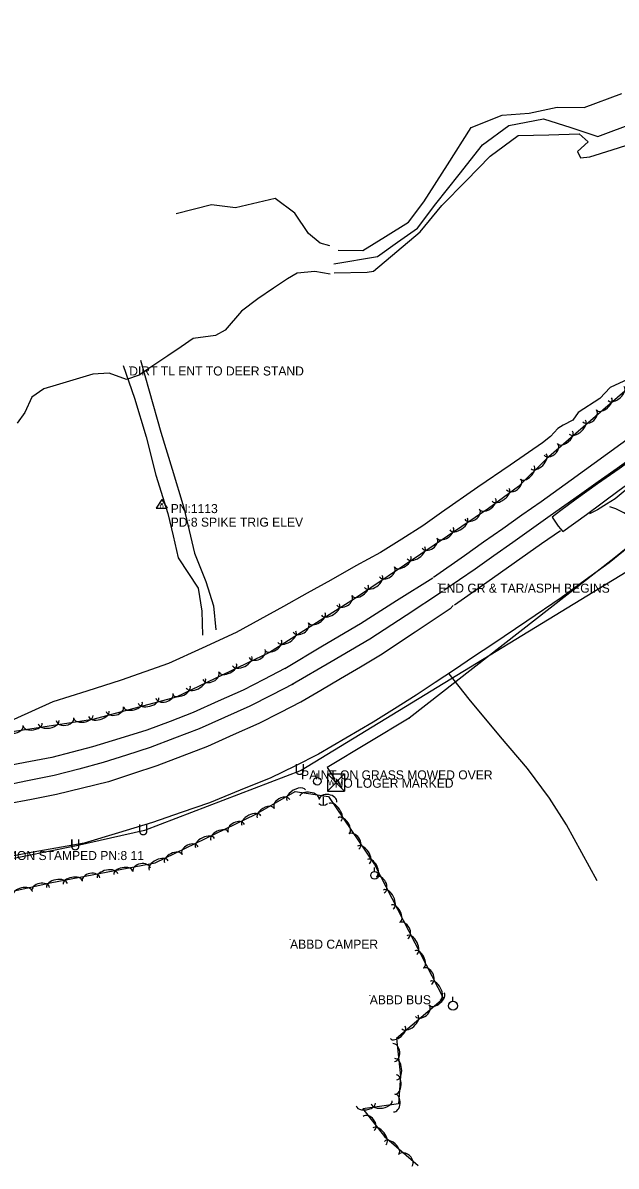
# Model space of a CAD drawing. Extents: x 1451369 to 1458940, y 1868647 to 1875095.
# Drawn here: x 1453703 to 1454031, y 1870905 to 1871537 of the extents above; entities that cross this region are included whole.
import ezdxf

# ---------------------------------------------------------------- set-up
doc = ezdxf.new("R2010")
doc.units = 0
for name, color, linetype in [('Default', 7, 'Continuous'), ('E_Const Align', 7, 'Continuous'), ('E_No Plot', 7, 'Continuous'), ('E_Proposed ROW and Easements', 7, 'Continuous'), ('E_Quarter Section Line', 7, 'Continuous'), ('E_ROW Point Number', 7, 'Continuous'), ('E_Station Offset', 7, 'Continuous'), ('E_Survey Point Number', 7, 'Continuous'), ('E_Tract Residual', 7, 'Continuous'), ('S_EDGE_PAVEMENT', 7, 'Continuous'), ('S_EXIST_ROW', 7, 'Continuous'), ('S_PARKING', 7, 'Continuous'), ('S_PAVEMENT_CROWN', 7, 'Continuous'), ('S_PRIMARY_CTL_ANNOT', 7, 'Continuous'), ('S_SECONDARY_CTL_ANNOT', 7, 'Continuous'), ('S_SURVEY_TEXT_ANNOT', 7, 'Continuous'), ('S_TRAILS', 7, 'Continuous'), ('S_UNDERGROUND_CABLE_ANNOT', 7, 'Continuous'), ('S_WATER_UTILITIES_ANNOT', 7, 'Continuous')]:
    doc.layers.add(name, color=color, linetype=linetype)

msp = doc.modelspace()

# ---------------------------------------------------------------- linework, layer by layer
at = {"layer": 'E_Const Align'}
for p, q in [((1453865.48, 1871119.86), (1453865.48, 1871121.97)), ((1453868.77, 1871109.2), (1453868.77, 1871104.47)), ((1453897.18, 1871067.82), (1453897.18, 1871069.93)), ((1453940.55, 1870996.01), (1453940.55, 1870998.49))]:
    msp.add_line(p, q, dxfattribs=at)
for centre, radius in [((1453865.6, 1871117.72), 2.13), ((1453897.31, 1871065.68), 2.13), ((1453940.7, 1870993.49), 2.5)]:
    msp.add_circle(centre, radius, dxfattribs=at)
msp.add_arc((1453868.83, 1871107.9), 3.41, 226.39718, 313.60282, dxfattribs=at)
at = {"layer": 'E_No Plot'}
for points in [[(1454029.66, 1871241.04), (1454029.66, 1871241.09), (1454029.66, 1871241.04), (1454029.61, 1871241.04), (1454029.66, 1871241.04), (1454029.66, 1871240.99), (1454029.66, 1871241.04), (1454029.71, 1871241.04)], [(1453916.5, 1871152.6), (1453916.5, 1871152.65), (1453916.5, 1871152.6), (1453916.45, 1871152.6), (1453916.5, 1871152.6), (1453916.5, 1871152.55), (1453916.5, 1871152.6), (1453916.55, 1871152.6)], [(1453871.11, 1871125.35), (1453871.11, 1871125.4), (1453871.11, 1871125.35), (1453871.06, 1871125.35), (1453871.11, 1871125.35), (1453871.11, 1871125.3), (1453871.11, 1871125.35), (1453871.16, 1871125.35)], [(1453875.2, 1871119.13), (1453875.2, 1871119.18), (1453875.2, 1871119.13), (1453875.15, 1871119.13), (1453875.2, 1871119.13), (1453875.2, 1871119.08), (1453875.2, 1871119.13), (1453875.25, 1871119.13)]]:
    msp.add_lwpolyline(points, dxfattribs=at)
at = {"layer": 'E_Proposed ROW and Easements'}
for points in [[(1453761.61, 1871347.23), (1453761.61, 1871347.28), (1453761.61, 1871347.23), (1453761.56, 1871347.23), (1453761.61, 1871347.23), (1453761.61, 1871347.18), (1453761.61, 1871347.23), (1453761.66, 1871347.23)], [(1453932.64, 1871227.05), (1453932.64, 1871227.1), (1453932.64, 1871227.05), (1453932.59, 1871227.05), (1453932.64, 1871227.05), (1453932.64, 1871227), (1453932.64, 1871227.05), (1453932.69, 1871227.05)], [(1453850.57, 1871030.07), (1453850.57, 1871030.12), (1453850.57, 1871030.07), (1453850.52, 1871030.07), (1453850.57, 1871030.07), (1453850.57, 1871030.02), (1453850.57, 1871030.07), (1453850.62, 1871030.07)], [(1453894.65, 1870999.32), (1453894.65, 1870999.37), (1453894.65, 1870999.32), (1453894.6, 1870999.32), (1453894.65, 1870999.32), (1453894.65, 1870999.27), (1453894.65, 1870999.32), (1453894.7, 1870999.32)]]:
    msp.add_lwpolyline(points, dxfattribs=at)
at = {"layer": 'E_Quarter Section Line'}
for p, q in [((1454074.79, 1871277.88), (1454029.66, 1871241.04)), ((1454029.66, 1871241.04), (1453916.5, 1871152.6)), ((1453916.5, 1871152.6), (1453871.11, 1871125.35)), ((1453871.11, 1871125.35), (1453875.2, 1871119.13)), ((1453871.33, 1871121.79), (1453880.67, 1871121.79)), ((1453871.33, 1871121.79), (1453871.33, 1871112.29)), ((1453871.33, 1871121.79), (1453880.67, 1871112.29)), ((1453880.67, 1871121.79), (1453871.33, 1871112.29)), ((1453880.67, 1871121.79), (1453880.67, 1871112.29)), ((1453871.33, 1871112.29), (1453880.67, 1871112.29))]:
    msp.add_line(p, q, dxfattribs=at)
at = {"layer": 'E_ROW Point Number'}
for points in [[(1454039.82, 1871337.12), (1453992.45, 1871296.2), (1453976.82, 1871280.78), (1453960.32, 1871268.68), (1453922.85, 1871243.35), (1453886.25, 1871218.61), (1453839.09, 1871189.03), (1453787.52, 1871164.25), (1453741.45, 1871151.98), (1453664.24, 1871140.16), (1453599.61, 1871130.45), (1453561.1, 1871125.93), (1453518.5, 1871126.32), (1453491.52, 1871121.48), (1453464.98, 1871114.18), (1453434.82, 1871115.78), (1453406.63, 1871118.92), (1453377.62, 1871115.67), (1453346.72, 1871118.15), (1453318.09, 1871119.73), (1453254.46, 1871123.88)], [(1453227.7, 1871010.68), (1453313.58, 1871012.86), (1453360.11, 1871017.03), (1453439.31, 1871020.86), (1453498.37, 1871025.17), (1453554.25, 1871028.97), (1453592.3, 1871033.98), (1453641.4, 1871044.5), (1453718.76, 1871061.66), (1453776, 1871072.6), (1453831.69, 1871099.59), (1453853.3, 1871112.04), (1453871.84, 1871109.31), (1453897.32, 1871071.61), (1453935.46, 1870997.61), (1453909.48, 1870975.45), (1453911.54, 1870954.62), (1453910.44, 1870939.28), (1453890.79, 1870936.46), (1453902.73, 1870921.25), (1453921.42, 1870905.04)]]:
    msp.add_lwpolyline(points, dxfattribs=at)
for centre, major_axis, ratio, start_param, end_param in [((1454030.95, 1871332.26), (4.44, 3.84), 0.550096, 3.141615, 6.283208), ((1454024.24, 1871326.46), (4.05, 3.49), 0.540715, 3.141614, 6.283207), ((1454016.27, 1871319.92), (3.75, 3.24), 0.685331, 3.141629, 6.283222), ((1454009.44, 1871313.67), (4.44, 3.84), 0.550096, 3.141615, 6.283208), ((1454002.73, 1871307.87), (4.05, 3.49), 0.540715, 3.141614, 6.283207), ((1453994.76, 1871301.34), (3.75, 3.24), 0.685331, 3.141629, 6.283222), ((1453988.01, 1871294.79), (4.18, 4.12), 0.550077, 3.141593, 6.283185), ((1453981.69, 1871288.57), (3.81, 3.75), 0.540697, 3.141593, 6.283185), ((1453974.31, 1871281.89), (3.99, 2.93), 0.686162, 3.141842, 6.283435), ((1453967.01, 1871276.22), (4.73, 3.47), 0.550763, 3.141745, 6.283338), ((1453951.27, 1871265.44), (4.11, 2.78), 0.685305, 3.141593, 6.283185), ((1453959.87, 1871270.98), (4.31, 3.16), 0.541371, 3.14174, 6.283333), ((1453943.75, 1871260.04), (4.86, 3.29), 0.550075, 3.141593, 6.283185), ((1453936.4, 1871255.07), (4.43, 2.99), 0.540695, 3.141593, 6.283185), ((1453927.72, 1871249.52), (4.11, 2.78), 0.685305, 3.141593, 6.283185), ((1453920.2, 1871244.12), (4.86, 3.29), 0.550075, 3.141593, 6.283185), ((1453904.17, 1871233.6), (4.11, 2.78), 0.685305, 3.141593, 6.283185), ((1453912.85, 1871239.15), (4.43, 2.99), 0.540695, 3.141593, 6.283185), ((1453896.65, 1871228.19), (4.86, 3.29), 0.550075, 3.141593, 6.283185), ((1453889.3, 1871223.23), (4.43, 2.99), 0.540695, 3.141593, 6.283185), ((1453880.59, 1871217.87), (4.2, 2.63), 0.685304, 3.141593, 6.283185), ((1453872.89, 1871212.73), (4.97, 3.12), 0.550075, 3.141593, 6.283185), ((1453856.51, 1871202.76), (4.2, 2.63), 0.685304, 3.141593, 6.283185), ((1453865.37, 1871208.02), (4.53, 2.84), 0.540694, 3.141593, 6.283185), ((1453848.8, 1871197.62), (4.97, 3.12), 0.550075, 3.141593, 6.283185), ((1453841.29, 1871192.91), (4.53, 2.84), 0.540694, 3.141593, 6.283185), ((1453824.08, 1871184.17), (5.29, 2.54), 0.550073, 3.141593, 6.283185), ((1453832.31, 1871188.41), (4.47, 2.15), 0.685302, 3.141593, 6.283185), ((1453816.09, 1871180.33), (4.82, 2.31), 0.540693, 3.141593, 6.283185), ((1453798.45, 1871171.86), (5.29, 2.54), 0.550073, 3.141593, 6.283185), ((1453806.69, 1871176.11), (4.47, 2.15), 0.685302, 3.141593, 6.283185), ((1453790.46, 1871168.02), (4.82, 2.31), 0.540693, 3.141593, 6.283185), ((1453763.64, 1871160.09), (5.17, 1.38), 0.54069, 3.141593, 6.283185), ((1453772.21, 1871162.37), (5.67, 1.51), 0.55007, 3.141593, 6.283185), ((1453781.09, 1871165.01), (4.79, 1.28), 0.685299, 3.141593, 6.283185), ((1453736.29, 1871153.33), (5.28, 0.81), 0.541194, 3.141797, 6.28339), ((1453744.74, 1871155.05), (5.67, 1.51), 0.55007, 3.141593, 6.283185), ((1453753.62, 1871157.69), (4.79, 1.28), 0.685299, 3.141593, 6.283185), ((1453698, 1871147.74), (4.89, 0.75), 0.685937, 3.141939, 6.283532), ((1453708.22, 1871149.04), (5.28, 0.81), 0.541194, 3.141797, 6.28339), ((1453716.98, 1871150.38), (5.8, 0.89), 0.550583, 3.141804, 6.283397), ((1453726.08, 1871152.03), (4.89, 0.75), 0.685937, 3.141939, 6.283532), ((1453853.96, 1871109.98), (-5.08, -2.93), 0.55017, 3.1416, 6.283193), ((1453861.31, 1871108.72), (-5.29, 0.78), 0.540695, 3.141593, 6.283185), ((1453871.46, 1871106.95), (-4.9, 0.72), 0.685306, 3.141593, 6.283185), ((1453837.01, 1871100.21), (-4.63, -2.67), 0.540788, 3.1416, 6.283193), ((1453846.07, 1871105.13), (-4.29, -2.47), 0.685423, 3.141605, 6.283198), ((1453875.25, 1871100.47), (-3.29, 4.86), 0.550071, 3.141593, 6.283185), ((1453829.07, 1871095.97), (-5.28, -2.56), 0.550079, 3.141593, 6.283185), ((1453880.22, 1871093.12), (-2.99, 4.43), 0.540691, 3.141593, 6.283185), ((1453811.46, 1871087.43), (-4.81, -2.33), 0.540699, 3.141593, 6.283185), ((1453820.85, 1871091.69), (-4.46, -2.16), 0.68531, 3.141593, 6.283185), ((1453803.48, 1871083.57), (-5.28, -2.56), 0.550079, 3.141593, 6.283185), ((1453885.77, 1871084.44), (-2.78, 4.11), 0.6853, 3.141593, 6.283185), ((1453785.88, 1871075.04), (-4.81, -2.33), 0.540699, 3.141593, 6.283185), ((1453795.27, 1871079.29), (-4.46, -2.16), 0.68531, 3.141593, 6.283185), ((1453891.17, 1871076.92), (-3.29, 4.86), 0.550071, 3.141593, 6.283185), ((1453768.42, 1871068.73), (-4.87, -0.93), 0.685309, 3.141593, 6.283185), ((1453777.9, 1871071.17), (-5.28, -2.56), 0.550079, 3.141593, 6.283185), ((1453895.9, 1871069.73), (-2.45, 4.75), 0.540691, 3.141593, 6.283185), ((1453740.5, 1871063.39), (-4.87, -0.93), 0.685309, 3.141593, 6.283185), ((1453749.54, 1871065.39), (-5.76, -1.1), 0.550078, 3.141593, 6.283185), ((1453758.25, 1871067.05), (-5.25, -1), 0.540698, 3.141593, 6.283185), ((1453900.39, 1871060.45), (-2.27, 4.4), 0.6853, 3.141593, 6.283185), ((1453702.57, 1871055.9), (-5.22, -1.16), 0.540698, 3.141593, 6.283185), ((1453712.68, 1871057.88), (-4.84, -1.07), 0.685309, 3.141593, 6.283185), ((1453721.62, 1871060.05), (-5.76, -1.1), 0.550078, 3.141593, 6.283185), ((1453730.33, 1871061.72), (-5.25, -1), 0.540698, 3.141593, 6.283185), ((1453904.87, 1871052.34), (-2.69, 5.22), 0.550072, 3.141593, 6.283185), ((1453908.93, 1871044.46), (-2.45, 4.75), 0.540691, 3.141593, 6.283185), ((1453913.42, 1871035.18), (-2.27, 4.4), 0.6853, 3.141593, 6.283185), ((1453917.89, 1871027.07), (-2.69, 5.22), 0.550072, 3.141593, 6.283185), ((1453921.95, 1871019.19), (-2.45, 4.75), 0.540691, 3.141593, 6.283185), ((1453926.44, 1871009.91), (-2.27, 4.4), 0.6853, 3.141593, 6.283185), ((1453930.91, 1871001.8), (-2.69, 5.22), 0.550072, 3.141593, 6.283185), ((1453931.75, 1870997.24), (4.07, 3.47), 0.540699, 3.141593, 6.283185), ((1453923.75, 1870990.75), (3.77, 3.22), 0.685311, 3.141593, 6.283185), ((1453916.87, 1870984.54), (4.47, 3.81), 0.55008, 3.141593, 6.283185), ((1453910.12, 1870978.79), (4.07, 3.47), 0.540699, 3.141593, 6.283185), ((1453907.86, 1870967.61), (-0.49, 4.93), 0.685303, 3.141593, 6.283185), ((1453909.03, 1870958.42), (-0.58, 5.84), 0.550073, 3.141593, 6.283185), ((1453909.08, 1870949.95), (0.38, 5.33), 0.540694, 3.141593, 6.283185), ((1453892.43, 1870938.83), (5.29, 0.76), 0.540698, 3.141596, 6.283189), ((1453901.21, 1870940.1), (5.81, 0.83), 0.550079, 3.141596, 6.283189), ((1453908.08, 1870939.69), (0.36, 4.94), 0.685305, 3.141593, 6.283185), ((1453894.07, 1870928.42), (-3.06, 3.9), 0.6853, 3.141593, 6.283185), ((1453899.99, 1870921.3), (-3.62, 4.62), 0.550071, 3.141593, 6.283185), ((1453906.73, 1870914.97), (-4.04, 3.5), 0.540693, 3.141584, 6.283177), ((1453914.34, 1870908.02), (-3.74, 3.25), 0.685302, 3.141578, 6.283171)]:
    msp.add_ellipse(centre, major_axis=major_axis, ratio=ratio, start_param=start_param, end_param=end_param, dxfattribs=at)
at = {"layer": 'E_Station Offset'}
for p, q in [((1453779.55, 1871273.7), (1453776.54, 1871268.75)), ((1453776.54, 1871268.75), (1453782.5, 1871268.75)), ((1453779.55, 1871273.7), (1453782.5, 1871268.75))]:
    msp.add_line(p, q, dxfattribs=at)
for radius in [0.311, 0.183, 0.103]:
    msp.add_circle((1453779.55, 1871271.09), radius, dxfattribs=at)
at = {"layer": 'E_Survey Point Number'}
for p, q in [((1454036.46, 1871233.42), (1453856.66, 1871123.76)), ((1453856.66, 1871123.76), (1453770.08, 1871090.42)), ((1453770.08, 1871090.42), (1453732.49, 1871082.08)), ((1453732.49, 1871082.08), (1453669.13, 1871069.18))]:
    msp.add_line(p, q, dxfattribs=at)
at = {"layer": 'E_Tract Residual'}
for points in [[(1453877.09, 1871411.59), (1453890.76, 1871411.31), (1453903.42, 1871419.17), (1453916.08, 1871427.02), (1453924.47, 1871438.24), (1453937.63, 1871458.88), (1453950.78, 1871479.51), (1453967.79, 1871486.3), (1453982.73, 1871487.41), (1453998.2, 1871490.78), (1454013.21, 1871490.57), (1454034.06, 1871498.26)], [(1453874.87, 1871399), (1453893.11, 1871399.42), (1453896.61, 1871400.04), (1453909.56, 1871410.87), (1453922.51, 1871421.71), (1453934.49, 1871436.35), (1453947.88, 1871449.93), (1453961.28, 1871463.5), (1453976.72, 1871474.97), (1453993.61, 1871475.46), (1454010.51, 1871475.95), (1454015.41, 1871471.43), (1454009.5, 1871466.12), (1454011.26, 1871462.69), (1454016.34, 1871463.18), (1454028.63, 1871467.06), (1454040.93, 1871470.94)], [(1453872.57, 1871414.01), (1453867.22, 1871415.52), (1453860.72, 1871420.84), (1453853.11, 1871432.09), (1453842.34, 1871440.22), (1453820.37, 1871435.03), (1453807.13, 1871436.59), (1453787.57, 1871431.61)], [(1453872.71, 1871398.29), (1453864.32, 1871399.7), (1453854.55, 1871398.89), (1453849.12, 1871395.78), (1453841.38, 1871390.55), (1453832.67, 1871384.66), (1453823.68, 1871377.88), (1453814.74, 1871367.31), (1453809.38, 1871364.41), (1453796.99, 1871362.65), (1453790.35, 1871358.16), (1453782.97, 1871353.17), (1453772.45, 1871346.06), (1453767.18, 1871342.49), (1453760.07, 1871340.05), (1453750.55, 1871343.49), (1453741.4, 1871342.98), (1453721.19, 1871336.91), (1453714.35, 1871334.81), (1453707.71, 1871330.32), (1453703.9, 1871321.79), (1453699.57, 1871315.92)], [(1454020.41, 1871062.69), (1454003.45, 1871093.65), (1453994.1, 1871108.43), (1453981.81, 1871124.74), (1453966.89, 1871142.39), (1453949.59, 1871163.17), (1453938.56, 1871177.12)]]:
    msp.add_lwpolyline(points, dxfattribs=at)
at = {"layer": 'S_EDGE_PAVEMENT'}
for points in [[(1454173.72, 1871404.14), (1454163.25, 1871396.68), (1454152.79, 1871389.23), (1454142.32, 1871381.77), (1454131.86, 1871374.32), (1454121.32, 1871366.84), (1454110.78, 1871359.35), (1454100.24, 1871351.87), (1454089.7, 1871344.39), (1454078.83, 1871336.64), (1454067.96, 1871328.89), (1454057.09, 1871321.14), (1454046.23, 1871313.39), (1454026.17, 1871298.9), (1454006.11, 1871284.4), (1453989.42, 1871272.42), (1453978.82, 1871264.94), (1453968.21, 1871257.46), (1453957.61, 1871249.98), (1453947.01, 1871242.51), (1453929.87, 1871230.39)], [(1454058.27, 1871297.14), (1454052.51, 1871304.9), (1454032.56, 1871290.65), (1454020.68, 1871282.23), (1454008.81, 1871273.8), (1454000.36, 1871267.57), (1453995.51, 1871263.87), (1453998.91, 1871258.87), (1454001.34, 1871255.84), (1454014.47, 1871265.24), (1454032.57, 1871278.79), (1454048.7, 1871290.33), (1454057.83, 1871296.85)], [(1454058.72, 1871297.11), (1454059.72, 1871295.46), (1454057.98, 1871294.09), (1454059.4, 1871292.13), (1454056.72, 1871285.74), (1454053.94, 1871281.16), (1454051.62, 1871278.54), (1454048.45, 1871277.23), (1454045.82, 1871279.05), (1454044.18, 1871280.81), (1454043.08, 1871280.66), (1454041.95, 1871282), (1454037.07, 1871279.5), (1454030.44, 1871274.03), (1454025.53, 1871270.97), (1454020.65, 1871267.99), (1454016.09, 1871265.75)], [(1454000.04, 1871256.25), (1453989.58, 1871249.01), (1453974.48, 1871238.33), (1453959.37, 1871227.64), (1453941.49, 1871215.18)], [(1453929.44, 1871230.14), (1453909.43, 1871217.48), (1453889.42, 1871204.82), (1453868.49, 1871192.38), (1453847.57, 1871179.95), (1453847.6, 1871180.06), (1453836.08, 1871174.12), (1453824.55, 1871168.18), (1453810.77, 1871161.96), (1453796.99, 1871155.74), (1453784.16, 1871150.88), (1453771.33, 1871146.01), (1453756.31, 1871141.37), (1453741.3, 1871136.73), (1453718.76, 1871130.94), (1453704.08, 1871128.1), (1453689.39, 1871125.27)], [(1453940.78, 1871214.89), (1453939.12, 1871213.05), (1453919.82, 1871200.23), (1453900.52, 1871187.42), (1453889.51, 1871180.93), (1453878.51, 1871174.44), (1453867.5, 1871167.95), (1453856.5, 1871161.47), (1453856.71, 1871161.58), (1453844.97, 1871155.61), (1453833.23, 1871149.65), (1453819.04, 1871143.34), (1453804.84, 1871137.04), (1453790.83, 1871131.61), (1453776.81, 1871126.18), (1453763.43, 1871121.83), (1453750.05, 1871117.48), (1453735.74, 1871113.9), (1453721.43, 1871110.31), (1453707.59, 1871107.68), (1453693.75, 1871105.05)]]:
    msp.add_lwpolyline(points, dxfattribs=at)
at = {"layer": 'S_EXIST_ROW'}
for points in [[(1453874.67, 1871403.94), (1453898.97, 1871408.04), (1453910.02, 1871415.94), (1453921.08, 1871423.84), (1453931.09, 1871437.12), (1453944.08, 1871453.49), (1453957.06, 1871469.87), (1453971.5, 1871480.54), (1453990.8, 1871484.27), (1454005.79, 1871479.41), (1454020.79, 1871474.55), (1454042.06, 1871482.37), (1454063.34, 1871490.19), (1454085, 1871497.84), (1454106.67, 1871505.5), (1454119.11, 1871513.46), (1454131.55, 1871521.42), (1454143.99, 1871529.38), (1454156.43, 1871537.34), (1454168.75, 1871534.39), (1454181.07, 1871531.43), (1454193.39, 1871528.48), (1454205.71, 1871525.52)], [(1454045.19, 1871343.73), (1454027.6, 1871335.62), (1454021.95, 1871329.57), (1454009.95, 1871321.69), (1454006.88, 1871317.49), (1454001.51, 1871314.72), (1453998.59, 1871312.84), (1453994.51, 1871308.41), (1453990.11, 1871304.89), (1453972.21, 1871292.7), (1453954.32, 1871280.5), (1453934.27, 1871266.47), (1453923.99, 1871259.13), (1453912.32, 1871251.68), (1453900.64, 1871244.22), (1453886.96, 1871236.94), (1453873.05, 1871228.96), (1453859.95, 1871221.72), (1453846.85, 1871214.48), (1453833.76, 1871207.23), (1453820.66, 1871199.99), (1453801.96, 1871191.45), (1453783.26, 1871182.9), (1453770.18, 1871178.28), (1453757.09, 1871173.66), (1453738.17, 1871167.62), (1453719.25, 1871161.58), (1453697.72, 1871151.97)], [(1454042.87, 1871251.45), (1454027.01, 1871238.63), (1454013.72, 1871228.94), (1454000.43, 1871219.25), (1453981.52, 1871206.38), (1453962.62, 1871193.5), (1453952.02, 1871186.48), (1453941.42, 1871179.46), (1453930.82, 1871172.44), (1453920.23, 1871165.42), (1453908.36, 1871157.88), (1453896.5, 1871150.34), (1453881.4, 1871141.52), (1453866.29, 1871132.7), (1453853.14, 1871126.13), (1453839.99, 1871119.57), (1453822.98, 1871112.72), (1453805.97, 1871105.87), (1453790.24, 1871100.35), (1453774.52, 1871094.82), (1453755.57, 1871089.19), (1453736.63, 1871083.56), (1453720.96, 1871080.71), (1453705.28, 1871077.87), (1453680.9, 1871073.2)]]:
    msp.add_lwpolyline(points, dxfattribs=at)
at = {"layer": 'S_PARKING'}
msp.add_ellipse((1454018.86, 1871237.67), major_axis=(-17.15, 28.44), ratio=0.985488, start_param=4.654519, end_param=5.470219, dxfattribs=at)
at = {"layer": 'S_PAVEMENT_CROWN'}
for points in [[(1454179.61, 1871396.18), (1454169.23, 1871388.84), (1454158.84, 1871381.49), (1454148.46, 1871374.14), (1454138.08, 1871366.8), (1454127.34, 1871359.17), (1454116.6, 1871351.55), (1454105.86, 1871343.93), (1454095.11, 1871336.3), (1454084.38, 1871328.63), (1454073.65, 1871320.95), (1454062.91, 1871313.27), (1454052.18, 1871305.6), (1454041.79, 1871298.22), (1454031.39, 1871290.85), (1454021, 1871283.47), (1454010.6, 1871276.1), (1453994.45, 1871264.5), (1453984.08, 1871257.16), (1453973.71, 1871249.81), (1453963.34, 1871242.47), (1453952.97, 1871235.12), (1453935.67, 1871223.29)], [(1453934.84, 1871222.64), (1453914.79, 1871209.45), (1453894.74, 1871196.27), (1453873.27, 1871183.76), (1453851.8, 1871171.26), (1453852.5, 1871171.61), (1453840.36, 1871165.42), (1453828.22, 1871159.22), (1453814.28, 1871152.95), (1453800.34, 1871146.68), (1453786.72, 1871141.52), (1453773.09, 1871136.36), (1453760.14, 1871132.2), (1453747.18, 1871128.05), (1453733.66, 1871124.46), (1453720.13, 1871120.87), (1453705.26, 1871117.89), (1453690.39, 1871114.91)]]:
    msp.add_lwpolyline(points, dxfattribs=at)
at = {"layer": 'S_TRAILS'}
for points in [[(1453767.92, 1871350.69), (1453772.69, 1871333.78), (1453779.11, 1871310.85), (1453785.42, 1871290.42), (1453791.79, 1871268.92), (1453794.78, 1871256.43), (1453797.76, 1871243.94), (1453803.95, 1871228.28), (1453808.16, 1871214.7), (1453809.43, 1871201.52)], [(1453758.28, 1871347.83), (1453764.47, 1871329.74), (1453770.97, 1871308.38), (1453776.24, 1871287.05), (1453782.9, 1871265.79), (1453785.81, 1871253.54), (1453788.73, 1871241.28), (1453799.72, 1871224.62), (1453801.69, 1871211.87), (1453802.1, 1871198.49)]]:
    msp.add_lwpolyline(points, dxfattribs=at)

# ---------------------------------------------------------------- texts
at = {"layer": 'Default'}
for p in [(1453853.03, 1871121.22), (1453766.45, 1871087.87), (1453728.86, 1871079.53)]:
    msp.add_text('U', height=6, rotation=360, dxfattribs=at).set_placement(p)
at = {"layer": 'E_Quarter Section Line'}
msp.add_text('W M', height=3, rotation=360, dxfattribs=at).set_placement((1453871.53, 1871115.55))
at = {"layer": 'E_Station Offset'}
msp.add_text('TV', height=1.5, rotation=360, dxfattribs=at).set_placement((1453778.35, 1871269.08))
at = {"layer": 'S_PRIMARY_CTL_ANNOT'}
msp.add_text('PD:STD AHTD MON STAMPED PN:8 11', height=5, dxfattribs=at).set_placement((1453647.53, 1871074.13))
at = {"layer": 'S_SECONDARY_CTL_ANNOT'}
for s, p in [('PN:1113', (1453784.55, 1871266.09)), ('PD:8 SPIKE TRIG ELEV', (1453784.55, 1871258.59))]:
    msp.add_text(s, height=5, dxfattribs=at).set_placement(p)
at = {"layer": 'S_SURVEY_TEXT_ANNOT'}
for s, p in [('DIRT TL ENT TO DEER STAND', (1453761.61, 1871342.23)), ('END GR & TAR/ASPH BEGINS', (1453932.64, 1871222.05)), ('ABBD CAMPER', (1453850.57, 1871025.07)), ('ABBD BUS', (1453894.65, 1870994.32))]:
    msp.add_text(s, height=5, dxfattribs=at).set_placement(p)
at = {"layer": 'S_UNDERGROUND_CABLE_ANNOT'}
msp.add_text('PAINT ON GRASS MOWED OVER', height=5, dxfattribs=at).set_placement((1453856.66, 1871118.76))
at = {"layer": 'S_WATER_UTILITIES_ANNOT'}
msp.add_text('NO LOGER MARKED', height=5, dxfattribs=at).set_placement((1453875.2, 1871114.13))

doc.saveas('drawing.dxf')
